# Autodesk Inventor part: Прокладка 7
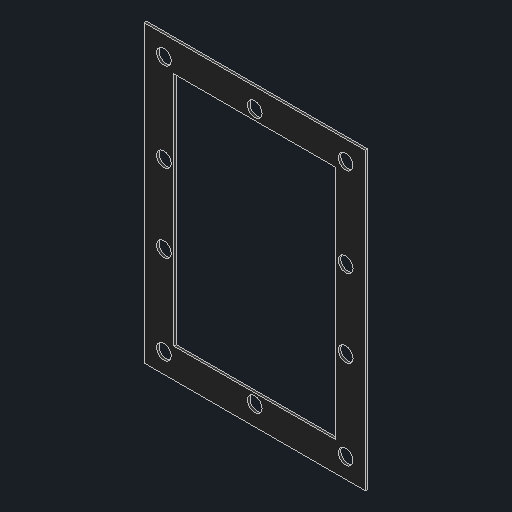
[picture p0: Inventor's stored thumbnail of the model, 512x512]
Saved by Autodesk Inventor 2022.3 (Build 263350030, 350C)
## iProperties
Created: 2022-08
Part Number: Прокладка 7
Material: Резина
Document SubType Name: Modeling
Designer: Карташов
Density: 0.93 g/cm^3
Appearance: Резина — черная
Author: Карташов
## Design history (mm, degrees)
sketch "Эскиз1"
  geometry: L1 (-45, -60)-(-45, 60) reference; L2 (45, -60)-(-45, -60) reference; L3 (45, 60)-(45, -60) reference; L4 (-45, 60)-(45, 60) reference; L5 (33, -48)-(33, 48) reference; L6 (-33, -48)-(33, -48) reference; L7 (-33, 48)-(-33, -48) reference; L8 (33, 48)-(-33, 48) reference; L9 (45, -60)-(-45, -60) reference; L10 (45, 60)-(45, -60) reference; L11 (-45, 60)-(45, 60) reference; L12 (-45, -60)-(-45, 60) reference; C1 r 5 at (0, 52) reference; C2 r 5 at (37, 15.835) reference; C3 r 5 at (37, -52) reference; C4 r 5 at (-37, -15.835) reference; C5 r 5 at (-37, 52) reference; C6 r 5 at (-37, 15.835) reference; C7 r 5 at (-37, -52) reference; C8 r 5 at (37, -15.835) reference; C9 r 5 at (37, 52) reference; C10 r 5 at (0, -52) reference; C11 r 6 at (0, 0) reference; C12 r 3 at (37, 52) reference; C13 r 3 at (37, 15.835) reference; C14 r 3 at (37, -15.835) reference; C15 r 3 at (0, 52) reference; C16 r 3 at (-37, 52) reference; C17 r 3 at (-37, 15.835) reference; C18 r 3 at (-37, -15.835) reference; C19 r 3 at (-37, -52); C20 r 3 at (0, -52); C21 r 3 at (37, -52); 1 further point
  constraints: 3 centre point, 3 coincident
  dimensions: "d0" = 6 diameter of C19; "d1" = 6 diameter of C20; "d2" = 6 diameter of C21
extrude "Выдавливание1" new body sketch "Эскиз1" distance "d3" = 1; taper "d4" = 0 deg
node "Твердое тело1"
node "Ссылка1"
node "Ссылка2"
node "Ссылка3"
node "Ссылка4"
node "Ссылка5"
node "Ссылка6"
node "Ссылка7"
node "Ссылка8"
node "Ссылка9"
